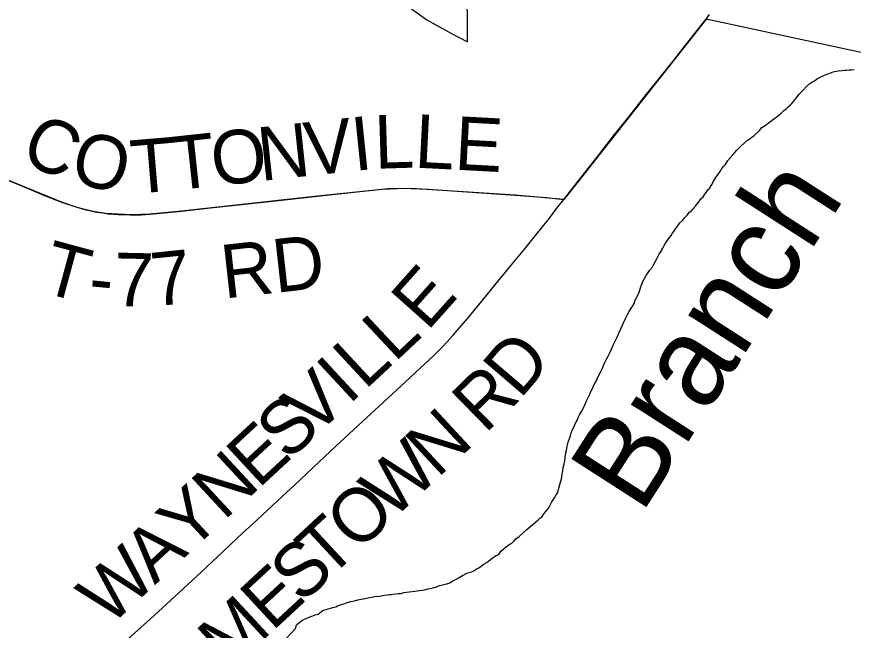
# Model space of a CAD drawing. Extents: x -5.4 to 49.9, y 13.2 to 48.4.
# Drawn here: x 28.445 to 29.333, y 42.924 to 43.576 of the extents above; entities that cross this region are included whole.
import ezdxf

# ---------------------------------------------------------------- set-up
doc = ezdxf.new("R2010")
doc.units = 0
for name, color, linetype in [('GM_X_City_Street', 7, 'Continuous'), ('GM_X_Corporation', 7, 'Continuous'), ('GM_X_County_Road', 7, 'Continuous'), ('GM_X_County_Road_Text', 7, 'Continuous'), ('GM_X_Minor_River', 7, 'Continuous'), ('GM_X_Minor_River_Text', 7, 'Continuous'), ('GM_X_Township_Road', 7, 'Continuous'), ('GM_X_Township_Road_Text', 7, 'Continuous')]:
    doc.layers.add(name, color=color, linetype=linetype)

msp = doc.modelspace()

# ---------------------------------------------------------------- linework, layer by layer
at = {"layer": 'GM_X_City_Street'}
msp.add_lwpolyline([(29.17703, 43.57322), (29.18074, 43.5781)], dxfattribs=at)
at = {"layer": 'GM_X_Corporation'}
for points in [[(28.19911, 43.96243), (28.49325, 43.85199), (28.74526, 43.84756), (28.80204, 43.59652), (28.81076, 43.59653), (28.81073, 43.61765), (28.83035, 43.61293), (28.85386, 43.59166), (28.87001, 43.57987), (28.88039, 43.57229), (28.90678, 43.55803), (28.92368, 43.5489), (28.9219, 43.87882), (29.02409, 43.80942), (29.02303, 43.86557), (29.18623, 43.75426), (29.28308, 43.68973), (29.34531, 43.6481)], [(29.38093, 43.52938), (29.17703, 43.57322), (29.03978, 43.39913), (29.0259, 43.3818), (28.97433, 43.38643), (28.86396, 43.3935), (28.83926, 43.39291), (28.76119, 43.38482), (28.61982, 43.3693), (28.58646, 43.36605), (28.5663, 43.36526), (28.53916, 43.36698), (28.52804, 43.36869), (28.52159, 43.37004), (28.5092, 43.37326), (28.49347, 43.37841), (28.43126, 43.40403)]]:
    msp.add_lwpolyline(points, dxfattribs=at)
at = {"layer": 'GM_X_County_Road'}
for points in [[(29.0259, 43.3818), (29.04018, 43.39963), (29.04932, 43.4114), (29.06361, 43.42941), (29.07987, 43.45057), (29.09541, 43.46993), (29.11381, 43.49345), (29.12459, 43.50709), (29.14438, 43.53174), (29.15011, 43.53904), (29.16455, 43.55762), (29.17703, 43.57322)], [(29.01856, 43.37231), (29.0259, 43.3818)], [(28.53926, 42.89375), (28.58679, 42.93661), (28.61254, 42.96003), (28.64127, 42.98662), (28.65843, 43.00285), (28.68508, 43.02795), (28.69515, 43.03719), (28.71074, 43.05145), (28.72714, 43.06665), (28.73982, 43.07856), (28.7593, 43.09684), (28.76607, 43.10324), (28.78377, 43.11978), (28.81201, 43.14597), (28.82987, 43.16235), (28.85775, 43.18804), (28.87864, 43.20753), (28.88816, 43.21647), (28.89789, 43.22612), (28.90176, 43.23017), (28.90841, 43.2376), (28.92582, 43.25789), (28.9357, 43.26989), (28.95257, 43.29059), (28.97036, 43.31216), (28.98457, 43.32942), (28.99594, 43.34341), (29.01055, 43.36196), (29.01856, 43.37231)]]:
    msp.add_lwpolyline(points, dxfattribs=at)
at = {"layer": 'GM_X_Minor_River'}
for points in [[(29.23639, 43.45805), (29.23983, 43.46029), (29.24289, 43.46254), (29.24595, 43.46478), (29.24901, 43.46741), (29.25206, 43.46927), (29.25474, 43.47152), (29.25704, 43.47378), (29.25972, 43.47603), (29.26202, 43.4779), (29.26432, 43.48015), (29.26623, 43.48165), (29.26815, 43.48353), (29.26969, 43.48541), (29.27123, 43.4873), (29.27315, 43.48955), (29.27584, 43.49332), (29.27968, 43.49746), (29.28352, 43.50159), (29.28735, 43.50497), (29.2904, 43.50684), (29.29231, 43.50758), (29.29537, 43.5102), (29.29805, 43.51169), (29.30109, 43.5128), (29.30376, 43.5139), (29.30643, 43.51501), (29.30871, 43.51575), (29.311, 43.51686), (29.31328, 43.5176), (29.31556, 43.51795), (29.31747, 43.51831), (29.32126, 43.51865), (29.32392, 43.519), (29.3262, 43.51897), (29.32886, 43.51932), (29.33151, 43.51929), (29.33417, 43.51964)], [(29.03179, 43.1279), (29.03296, 43.13093), (29.03415, 43.13548), (29.0357, 43.1385), (29.03725, 43.1419), (29.03842, 43.14417), (29.03997, 43.14719), (29.04114, 43.15021), (29.04269, 43.15324), (29.04462, 43.15663), (29.04811, 43.16343), (29.04967, 43.16722), (29.05199, 43.17213), (29.05354, 43.17515), (29.05471, 43.1778), (29.05587, 43.18044), (29.05742, 43.18347), (29.05859, 43.18611), (29.06013, 43.18875), (29.06169, 43.19215), (29.06324, 43.19518), (29.06518, 43.19896), (29.06711, 43.20273), (29.06868, 43.20727), (29.071, 43.21143), (29.07294, 43.21521), (29.07488, 43.21898), (29.07643, 43.22276), (29.07799, 43.22617), (29.07954, 43.22919), (29.08109, 43.23259), (29.08264, 43.23561), (29.0842, 43.23978), (29.08653, 43.24431), (29.08925, 43.25074), (29.09157, 43.25527), (29.09352, 43.25943), (29.09545, 43.26283), (29.09738, 43.26622), (29.09931, 43.26886), (29.10085, 43.27151), (29.10126, 43.27416), (29.10319, 43.27718), (29.10435, 43.27944), (29.10591, 43.28323), (29.10748, 43.28777), (29.10982, 43.29458), (29.11331, 43.301), (29.11678, 43.30628), (29.11985, 43.30966), (29.12102, 43.31231), (29.12488, 43.31873), (29.12605, 43.32137), (29.12721, 43.32364), (29.12875, 43.3259), (29.13107, 43.33006), (29.13261, 43.3327), (29.13416, 43.33572), (29.13647, 43.33873), (29.13802, 43.34137), (29.13994, 43.34363), (29.14148, 43.3459), (29.14264, 43.34778), (29.14456, 43.35042), (29.14688, 43.35381), (29.14919, 43.35683), (29.15225, 43.35983), (29.15456, 43.36247), (29.15686, 43.3651), (29.15955, 43.36811), (29.16146, 43.36961), (29.163, 43.37149), (29.16569, 43.3745), (29.16761, 43.37714), (29.16953, 43.3794), (29.17146, 43.38241), (29.17376, 43.38467), (29.17569, 43.3873), (29.17723, 43.38919), (29.17916, 43.3922), (29.18107, 43.3937), (29.18185, 43.39559), (29.18339, 43.39786), (29.18494, 43.40126), (29.18726, 43.40503), (29.18995, 43.40842), (29.19188, 43.41144), (29.19381, 43.41446), (29.19573, 43.41709), (29.19765, 43.41897), (29.19997, 43.42313), (29.20535, 43.42915), (29.20957, 43.43404), (29.21379, 43.43817), (29.21762, 43.44155), (29.22107, 43.44455), (29.22374, 43.44642), (29.22566, 43.44791), (29.22757, 43.44941), (29.2337, 43.45504), (29.23639, 43.45805)], [(28.72705, 42.91147), (28.74092, 42.92639), (28.74209, 42.93018), (28.74783, 42.93467), (28.75432, 42.93802), (28.75927, 42.93986), (28.76194, 42.94097), (28.76498, 42.9417), (28.76995, 42.94544), (28.77566, 42.94728), (28.78061, 42.94874), (28.78365, 42.94947), (28.78556, 42.9502), (28.78975, 42.95168), (28.79241, 42.95241), (28.79584, 42.95389), (28.79965, 42.95498), (28.80345, 42.9557), (28.80726, 42.9568), (28.81068, 42.95752), (28.81486, 42.95823), (28.81942, 42.95932), (28.82513, 42.9604), (28.83006, 42.96072), (28.83501, 42.9618), (28.83843, 42.96215), (28.84071, 42.9625), (28.8426, 42.96248), (28.84717, 42.96319), (28.84982, 42.96354), (28.85324, 42.9635), (28.85591, 42.96461), (28.8616, 42.9653), (28.86768, 42.966), (28.87262, 42.9667), (28.87566, 42.96705), (28.87756, 42.9674), (28.87946, 42.96776), (28.88137, 42.9685), (28.88403, 42.96885), (28.88707, 42.96958), (28.89088, 42.97067), (28.89392, 42.97178), (28.89697, 42.97251), (28.90001, 42.97323), (28.90267, 42.97396), (28.90496, 42.97469), (28.90802, 42.97694), (28.91298, 42.97954), (28.91832, 42.98252), (28.9229, 42.98513), (28.92785, 42.9866), (28.92975, 42.98733), (28.93166, 42.98845), (28.93396, 42.98995), (28.93624, 42.99106), (28.93854, 42.99294), (28.94122, 42.9948), (28.94389, 42.99629), (28.9458, 42.99779), (28.9481, 42.99966), (28.95078, 43.00153), (28.95421, 43.00378), (28.95688, 43.00489), (28.95919, 43.00828), (28.96341, 43.01203), (28.968, 43.0154), (28.97067, 43.01689), (28.97297, 43.01914), (28.97489, 43.0214), (28.97833, 43.02402), (28.98676, 43.03152), (28.98905, 43.0334), (28.99135, 43.03527), (28.99327, 43.03715), (28.99594, 43.03902), (28.99863, 43.04165), (29.00054, 43.04353), (29.00284, 43.04502), (29.00515, 43.04841), (29.00784, 43.0518), (29.01015, 43.05444), (29.01325, 43.06086), (29.01595, 43.06501), (29.01788, 43.06803), (29.01942, 43.07067), (29.02022, 43.0737), (29.0214, 43.07787), (29.02258, 43.08165), (29.02337, 43.08468), (29.02378, 43.0881), (29.02498, 43.09379), (29.0254, 43.0972), (29.0262, 43.10099), (29.02699, 43.1044), (29.0274, 43.10744), (29.02782, 43.11123), (29.02863, 43.1154), (29.02943, 43.11995), (29.03062, 43.12412), (29.03179, 43.1279)]]:
    msp.add_lwpolyline(points, dxfattribs=at)
at = {"layer": 'GM_X_Township_Road'}
msp.add_lwpolyline([(28.43126, 43.40403), (28.45092, 43.39565), (28.47444, 43.38591), (28.49347, 43.37841), (28.50875, 43.37339), (28.51371, 43.37197), (28.51828, 43.37074), (28.5239, 43.3695), (28.52977, 43.36835), (28.53631, 43.36737), (28.542, 43.36658), (28.54749, 43.36606), (28.55247, 43.36566), (28.56545, 43.36524), (28.57719, 43.3655), (28.58646, 43.36606), (28.59388, 43.36676), (28.61982, 43.36929), (28.65069, 43.37268), (28.71982, 43.38043), (28.76119, 43.38482), (28.80625, 43.38983), (28.83285, 43.39255), (28.84901, 43.39347), (28.85583, 43.39368), (28.86396, 43.3935), (28.88199, 43.3928), (28.97433, 43.38642), (29.00777, 43.38363), (29.0259, 43.3818)], dxfattribs=at)

# ---------------------------------------------------------------- texts
at = {"layer": 'GM_X_County_Road_Text'}
for s, rotation, p in [('E', 48.25908, (28.88088, 43.241)), ('L', 43.16202, (28.84602, 43.20798)), ('D', 49.45764, (28.97941, 43.16889)), ('L', 42.82977, (28.81459, 43.17884)), ('I', 42.83045, (28.79748, 43.16298)), ('V', 42.82271, (28.7608, 43.12899)), ('R', 44.35115, (28.94226, 43.13224)), ('S', 42.81896, (28.73268, 43.10293)), ('N', 42.86251, (28.89164, 43.08519)), ('E', 42.82747, (28.70151, 43.07404)), ('W', 42.82364, (28.84333, 43.04041)), ('N', 42.82284, (28.66484, 43.04005)), ('Y', 42.82284, (28.62816, 43.00607)), ('O', 42.81522, (28.80664, 43.00642)), ('T', 42.81889, (28.77547, 42.97753)), ('A', 42.82284, (28.59149, 42.97208)), ('W', 42.82401, (28.54321, 42.92733)), ('S', 42.81867, (28.74735, 42.95148)), ('E', 42.81889, (28.71618, 42.92259)), ('M', 42.81907, (28.67095, 42.88068))]:
    msp.add_text(s, height=0.05682, rotation=rotation, dxfattribs=at).set_placement(p)
at = {"layer": 'GM_X_Minor_River_Text'}
msp.add_text('Branch', height=0.094688, rotation=57.26628, dxfattribs=at).set_placement((29.10802, 43.04645))
at = {"layer": 'GM_X_Township_Road_Text'}
for s, height, rotation, p in [('C', 0.05682, 336.21821, (28.44658, 43.42313)), ('V', 0.05682, 6.13905, (28.75361, 43.40656)), ('I', 0.05682, 5.88847, (28.80325, 43.4119)), ('L', 0.05682, 1.80022, (28.82539, 43.41422)), ('L', 0.05682, 357.09308, (28.86664, 43.41557)), ('E', 0.05682, 356.93, (28.90904, 43.41342)), ('O', 0.05682, 6.1619, (28.65419, 43.39583)), ('N', 0.05682, 6.15716, (28.7039, 43.4012)), ('O', 0.05682, 346.47958, (28.4998, 43.40076)), ('T', 0.05682, 4.80517, (28.56812, 43.38757)), ('T', 0.05682, 6.1597, (28.61193, 43.39127)), ('RD', 0.056818, 6.39457, (28.66513, 43.27639)), ('T', 0.05682, 344.78811, (28.46877, 43.28408)), ('7', 0.05682, 358.77238, (28.54771, 43.26855)), ('7', 0.05682, 5.89345, (28.59027, 43.26811)), ('-', 0.05682, 354.46987, (28.51991, 43.27107))]:
    msp.add_text(s, height=height, rotation=rotation, dxfattribs=at).set_placement(p)

doc.saveas('drawing.dxf')
